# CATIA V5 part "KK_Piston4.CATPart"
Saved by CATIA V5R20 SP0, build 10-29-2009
Part number: Piston4
Bounding box of the stored display mesh (mm): x 38.513 to 52.047, y -76.696 to -42.982, z 33.904 to 105
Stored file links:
  G:\Khaled_CFAO_2011\ST2M\ST2M_GR1\msallin\Khaled\Version_Finale\KK_Piston4.CATPart
  C:\Users\Mathieu\Desktop\Think Motion\JOUG-MELEE2.CATProduct
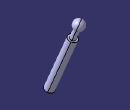
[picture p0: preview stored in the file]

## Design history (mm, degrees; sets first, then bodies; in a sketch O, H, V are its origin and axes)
External parameters (linked from other documents)
  `External.Taille du joug` = 100 mm
Set1
  Line1: linked copy from another document
  Line2: linked copy from another document
  Point1: linked copy from another document
Set2
  Plane1: type 2Lines, Element1 Line1, Element2 Line2
Body1 (main body)
  Sketch1 on Plane1, origin (70.7263, -40.514, 20.3771), H (0.4971, 0.8677, 0), V (-0.2105, 0.1206, 0.9701)
    point P1 (-39.3742, 15.5054)
    line L1 (-39.3742, 15.5054) -> (-35.3735, 14.341)
    line L2 (-35.3735, 14.341) -> (-20.0039, 67.1498)
    line L3 (-20.0039, 67.1498) -> (-21.6041, 67.6156)
    line L4 (-21.6041, 67.6156) -> (-18.8096, 77.2172)
    arc A1 centre (-20, 82.0734) radius 5 from (-18.8096, 77.2172) to (-18.6028, 86.8742) ccw
    point P6 (-20, 82.0734)
    point P7 (-18.6028, 86.8742)
    reference projected line E1 (-20, 82.0734) -> (-50, -21.0042) from Line2
    reference projected line E2 (-20, 82.0734) -> (-50, -21.0042) from Line2
    reference projected point E3 (-20, 82.0734) from Point1
    reference projected line E4 (-20, 82.0734) -> (-50, -21.0042) from Line2
    reference projected line E5 (-20, 82.0734) -> (-50, -21.0042) from Line2
    radius A1 = 5 {= `External.Taille du joug` /20}
    length L2 = 55 {= `External.Taille du joug` *(7/10-1/10-1/20)}
    angle L2 L1 = 90
    length L4 = 10 {= `External.Taille du joug` /10}
    distance L2 E1 = 4.1667 {= `External.Taille du joug` /24}
    distance L4 E2 = 2.5 {= `External.Taille du joug` /40}
    distance P6 E3 = 0
    distance P7 E4 = 0
    distance P1 E5 = 0
    parallelism: L3 L1, L4 L2
  Shaft1: profile Sketch1, axis Line2, angle 360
